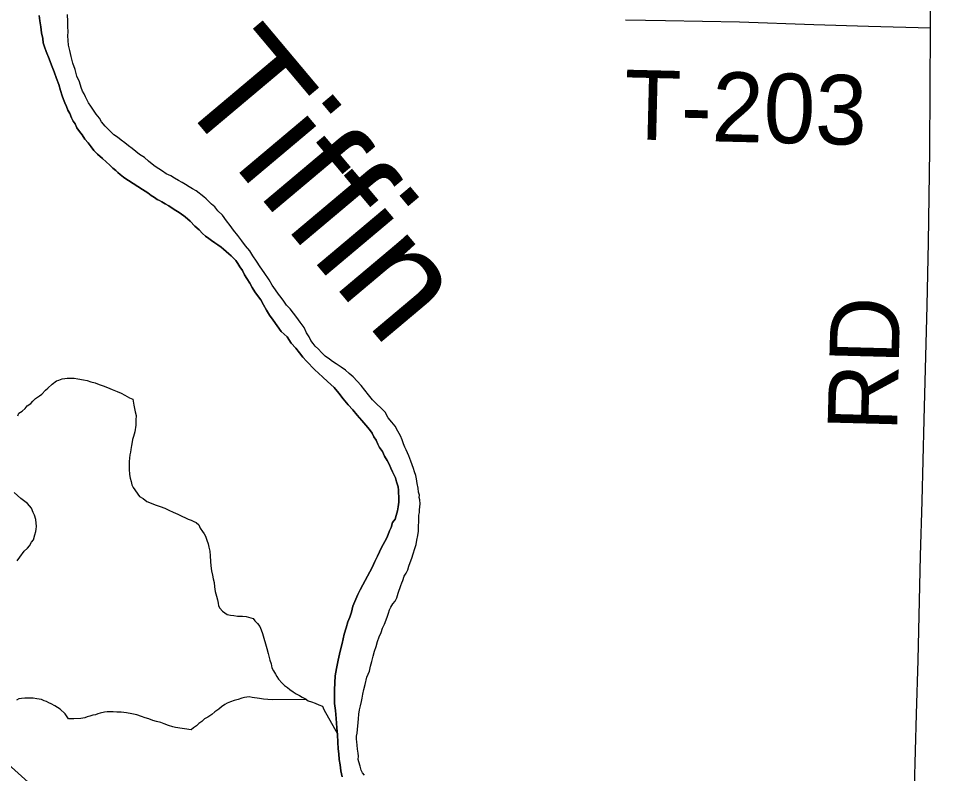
# Model space of a CAD drawing. Extents: x 2.1 to 73.9, y 4 to 26.
# Drawn here: x 47.8205 to 48.1962, y 24.0542 to 24.3627 of the extents above; entities that cross this region are included whole.
import ezdxf

# ---------------------------------------------------------------- set-up
doc = ezdxf.new("R2010")
doc.units = 0
for name, color, linetype in [('GM_X_County_Road', 7, 'Continuous'), ('GM_X_County_Road_Text', 7, 'Continuous'), ('GM_X_Major_River', 7, 'Continuous'), ('GM_X_Major_River_Text', 7, 'Continuous'), ('GM_X_Minor_River', 7, 'Continuous'), ('GM_X_State_Route', 7, 'Continuous'), ('GM_X_Township_Road', 7, 'Continuous'), ('GM_X_Township_Road_Text', 7, 'Continuous')]:
    doc.layers.add(name, color=color, linetype=linetype)

msp = doc.modelspace()

# ---------------------------------------------------------------- linework, layer by layer
at = {"layer": 'GM_X_County_Road'}
for points in [[(48.19325, 24.35883), (48.19329, 24.38494), (48.1935, 24.41821), (48.19357, 24.44027), (48.19356, 24.46205), (48.19359, 24.48068), (48.19358, 24.49156), (48.19371, 24.51674), (48.19388, 24.55155), (48.19407, 24.57673), (48.19423, 24.59599), (48.19435, 24.61584), (48.19457, 24.64257), (48.19491, 24.6777), (48.19507, 24.69386), (48.1954, 24.72618), (48.19554, 24.74546), (48.1958, 24.76317), (48.19622, 24.80171)], [(48.18678, 24.0485), (48.18765, 24.07851), (48.18821, 24.10057), (48.18883, 24.12481), (48.18921, 24.14315), (48.18984, 24.16551), (48.19072, 24.19876), (48.1919, 24.24538), (48.19247, 24.27117), (48.19307, 24.30878), (48.19325, 24.35883)]]:
    msp.add_lwpolyline(points, dxfattribs=at)
at = {"layer": 'GM_X_Major_River'}
for points in [[(47.82904, 24.36382), (47.82937, 24.36172), (47.82969, 24.35925), (47.83, 24.35677), (47.83052, 24.35448), (47.83066, 24.35277), (47.83119, 24.35104), (47.8319, 24.34913), (47.83316, 24.34625), (47.83404, 24.34357), (47.83511, 24.34088), (47.83618, 24.3382), (47.83707, 24.3357), (47.83777, 24.33322), (47.83848, 24.33111), (47.83901, 24.32958), (47.83954, 24.32824), (47.84026, 24.3267), (47.8408, 24.32517), (47.84152, 24.32382), (47.84224, 24.32209), (47.84296, 24.32075)], [(47.84296, 24.32075), (47.84224, 24.32209), (47.84152, 24.32382), (47.8408, 24.32517), (47.84026, 24.3267), (47.83954, 24.32824), (47.83901, 24.32958), (47.83848, 24.33111), (47.83777, 24.33322), (47.83707, 24.3357), (47.83618, 24.3382), (47.83511, 24.34088), (47.83404, 24.34357), (47.83316, 24.34625), (47.8319, 24.34913), (47.83119, 24.35104), (47.83066, 24.35277), (47.83052, 24.35448), (47.83, 24.35677), (47.82969, 24.35925), (47.82937, 24.36172), (47.82904, 24.36382)], [(47.94448, 24.22627), (47.94318, 24.22763), (47.94189, 24.2288), (47.94096, 24.22996), (47.94004, 24.23113), (47.93932, 24.23266), (47.93822, 24.23421), (47.93733, 24.23651), (47.93567, 24.23864), (47.93439, 24.24057), (47.93292, 24.24232), (47.93163, 24.24406), (47.93015, 24.24562), (47.92905, 24.24716), (47.92795, 24.24871), (47.92685, 24.25007), (47.92556, 24.25181), (47.92428, 24.25374), (47.923, 24.25586), (47.92099, 24.25895), (47.91934, 24.26127), (47.91788, 24.26359), (47.91641, 24.26571), (47.91514, 24.26783), (47.91329, 24.26978), (47.91182, 24.27191), (47.91017, 24.27404), (47.90851, 24.27617), (47.90704, 24.2781), (47.90557, 24.28004), (47.90392, 24.28236), (47.90206, 24.28412), (47.90077, 24.28567), (47.89947, 24.28684), (47.89817, 24.28801), (47.89725, 24.28898), (47.89632, 24.28977), (47.89315, 24.29232), (47.89165, 24.29311), (47.89034, 24.29391), (47.88885, 24.29489), (47.88754, 24.29569), (47.88604, 24.29648), (47.88435, 24.29748), (47.88286, 24.29846), (47.88098, 24.29927), (47.87949, 24.30026), (47.87799, 24.30125), (47.8765, 24.30223), (47.87519, 24.30322), (47.8737, 24.30439), (47.87203, 24.30595), (47.86997, 24.30715), (47.86848, 24.30832), (47.86699, 24.3095), (47.8655, 24.31068), (47.86401, 24.31185), (47.86252, 24.31303), (47.86103, 24.31421), (47.85954, 24.3152), (47.85824, 24.31656), (47.85713, 24.31754), (47.85602, 24.3187), (47.85454, 24.32045), (47.85363, 24.32199), (47.85234, 24.32354), (47.85124, 24.32528), (47.85014, 24.32683), (47.84923, 24.32818), (47.8485, 24.32953), (47.84796, 24.33068), (47.84742, 24.33183), (47.84669, 24.33299), (47.84616, 24.33452), (47.84546, 24.33682), (47.84438, 24.33913), (47.84368, 24.3418), (47.8428, 24.34448), (47.84211, 24.34716), (47.8416, 24.34964), (47.84108, 24.35174), (47.84094, 24.35364), (47.8408, 24.35555), (47.84084, 24.35725), (47.84071, 24.35935), (47.84076, 24.36143), (47.84064, 24.36428)], [(47.94448, 24.22627), (47.94318, 24.22763), (47.94189, 24.2288), (47.94096, 24.22996), (47.94004, 24.23113), (47.93932, 24.23266), (47.93822, 24.23421), (47.93733, 24.23651), (47.93567, 24.23864), (47.93439, 24.24057), (47.93292, 24.24232), (47.93163, 24.24406), (47.93015, 24.24562), (47.92905, 24.24716), (47.92795, 24.24871), (47.92685, 24.25007), (47.92556, 24.25181), (47.92428, 24.25374), (47.923, 24.25586), (47.92099, 24.25895), (47.91934, 24.26127), (47.91788, 24.26359), (47.91641, 24.26571), (47.91514, 24.26783), (47.91329, 24.26978), (47.91182, 24.27191), (47.91017, 24.27404), (47.90851, 24.27617), (47.90704, 24.2781), (47.90557, 24.28004), (47.90392, 24.28236), (47.90206, 24.28412), (47.90077, 24.28567), (47.89947, 24.28684), (47.89817, 24.28801), (47.89725, 24.28898), (47.89632, 24.28977), (47.89315, 24.29232), (47.89165, 24.29311), (47.89034, 24.29391), (47.88885, 24.29489), (47.88754, 24.29569), (47.88604, 24.29648), (47.88435, 24.29748), (47.88286, 24.29846), (47.88098, 24.29927), (47.87949, 24.30026), (47.87799, 24.30125), (47.8765, 24.30223), (47.87519, 24.30322), (47.8737, 24.30439), (47.87203, 24.30595), (47.86997, 24.30715), (47.86848, 24.30832), (47.86699, 24.3095), (47.8655, 24.31068), (47.86401, 24.31185), (47.86252, 24.31303), (47.86103, 24.31421), (47.85954, 24.3152), (47.85824, 24.31656), (47.85713, 24.31754), (47.85602, 24.3187), (47.85454, 24.32045), (47.85363, 24.32199), (47.85234, 24.32354), (47.85124, 24.32528), (47.85014, 24.32683), (47.84923, 24.32818), (47.8485, 24.32953), (47.84796, 24.33068), (47.84742, 24.33183), (47.84669, 24.33299), (47.84616, 24.33452), (47.84546, 24.33682), (47.84438, 24.33913), (47.84368, 24.3418), (47.8428, 24.34448), (47.84211, 24.34716), (47.8416, 24.34964), (47.84108, 24.35174), (47.84094, 24.35364), (47.8408, 24.35555), (47.84084, 24.35725), (47.84071, 24.35935), (47.84076, 24.36143), (47.84064, 24.36428)], [(47.84296, 24.32075), (47.84369, 24.31959), (47.84441, 24.31805), (47.84552, 24.3165), (47.84662, 24.31515), (47.84772, 24.31341), (47.84901, 24.31186), (47.8503, 24.3103), (47.8514, 24.30876), (47.85288, 24.3072), (47.85492, 24.30544), (47.85641, 24.30407), (47.85789, 24.30271), (47.85919, 24.30153), (47.86031, 24.30056), (47.86124, 24.29977), (47.86217, 24.29899), (47.86347, 24.29782), (47.8644, 24.29722), (47.86552, 24.29644), (47.87132, 24.29287), (47.87338, 24.29149), (47.87487, 24.29031), (47.87618, 24.28952), (47.8773, 24.28873), (47.87824, 24.28833), (47.87917, 24.28774), (47.88048, 24.28694), (47.88198, 24.28615), (47.88385, 24.28496), (47.88665, 24.28318), (47.8887, 24.28161), (47.89075, 24.27985), (47.8926, 24.2779), (47.89446, 24.27633), (47.89575, 24.27478), (47.89705, 24.2738), (47.89836, 24.27282), (47.89948, 24.27203), (47.90078, 24.27105), (47.90209, 24.27025), (47.9034, 24.26927), (47.90433, 24.26849), (47.90544, 24.26751), (47.90656, 24.26653), (47.90749, 24.26575), (47.90841, 24.26478), (47.90934, 24.2638), (47.91026, 24.26264), (47.91098, 24.26129), (47.91208, 24.25975), (47.91299, 24.25802), (47.9139, 24.25647), (47.91518, 24.25454), (47.91609, 24.25281), (47.91718, 24.25107), (47.91828, 24.24953), (47.91957, 24.24779), (47.92066, 24.24567), (47.92193, 24.24355), (47.92321, 24.24143), (47.92468, 24.23949), (47.92633, 24.23717), (47.92798, 24.23485), (47.9304, 24.2327), (47.93204, 24.23), (47.93389, 24.22806), (47.93536, 24.22612), (47.93683, 24.22437), (47.93831, 24.22263), (47.94164, 24.21912), (47.94313, 24.21776), (47.94499, 24.21619), (47.94684, 24.21444), (47.94963, 24.2119), (47.95147, 24.20957), (47.95331, 24.20725), (47.95534, 24.20492), (47.95718, 24.20278), (47.95903, 24.20065), (47.96087, 24.19851), (47.96253, 24.19657), (47.96401, 24.19482), (47.96511, 24.19328), (47.96583, 24.19174), (47.96675, 24.19039), (47.96747, 24.18885), (47.96819, 24.1875), (47.96929, 24.18577), (47.97019, 24.18385), (47.97129, 24.18211), (47.97201, 24.18057), (47.97273, 24.17904), (47.97345, 24.1775), (47.97399, 24.17635), (47.97472, 24.175), (47.97506, 24.17347), (47.97576, 24.17136), (47.97592, 24.17003), (47.9759, 24.16908), (47.97604, 24.16718)], [(47.97604, 24.16718), (47.9759, 24.16908), (47.97592, 24.17003), (47.97576, 24.17136), (47.97506, 24.17347), (47.97472, 24.175), (47.97399, 24.17635), (47.97345, 24.1775), (47.97273, 24.17904), (47.97201, 24.18057), (47.97129, 24.18211), (47.97019, 24.18385), (47.96929, 24.18577), (47.96819, 24.1875), (47.96747, 24.18885), (47.96675, 24.19039), (47.96583, 24.19174), (47.96511, 24.19328), (47.96401, 24.19482), (47.96253, 24.19657), (47.96087, 24.19851), (47.95903, 24.20065), (47.95718, 24.20278), (47.95534, 24.20492), (47.95331, 24.20725), (47.95147, 24.20957), (47.94963, 24.2119), (47.94684, 24.21444), (47.94499, 24.21619), (47.94313, 24.21776), (47.94164, 24.21912), (47.93831, 24.22263), (47.93683, 24.22437), (47.93536, 24.22612), (47.93389, 24.22806), (47.93204, 24.23), (47.9304, 24.2327), (47.92798, 24.23485), (47.92633, 24.23717), (47.92468, 24.23949), (47.92321, 24.24143), (47.92193, 24.24355), (47.92066, 24.24567), (47.91957, 24.24779), (47.91828, 24.24953), (47.91718, 24.25107), (47.91609, 24.25281), (47.91518, 24.25454), (47.9139, 24.25647), (47.91299, 24.25802), (47.91208, 24.25975), (47.91098, 24.26129), (47.91026, 24.26264), (47.90934, 24.2638), (47.90841, 24.26478), (47.90749, 24.26575), (47.90656, 24.26653), (47.90544, 24.26751), (47.90433, 24.26849), (47.9034, 24.26927), (47.90209, 24.27025), (47.90078, 24.27105), (47.89948, 24.27203), (47.89836, 24.27282), (47.89705, 24.2738), (47.89575, 24.27478), (47.89446, 24.27633), (47.8926, 24.2779), (47.89075, 24.27985), (47.8887, 24.28161), (47.88665, 24.28318), (47.88385, 24.28496), (47.88198, 24.28615), (47.88048, 24.28694), (47.87917, 24.28774), (47.87824, 24.28833), (47.8773, 24.28873), (47.87618, 24.28952), (47.87487, 24.29031), (47.87338, 24.29149), (47.87132, 24.29287), (47.86552, 24.29644), (47.8644, 24.29722), (47.86347, 24.29782), (47.86217, 24.29899), (47.86124, 24.29977), (47.86031, 24.30056), (47.85919, 24.30153), (47.85789, 24.30271), (47.85641, 24.30407), (47.85492, 24.30544), (47.85288, 24.3072), (47.8514, 24.30876), (47.8503, 24.3103), (47.84901, 24.31186), (47.84772, 24.31341), (47.84662, 24.31515), (47.84552, 24.3165), (47.84441, 24.31805), (47.84369, 24.31959), (47.84296, 24.32075)], [(47.95946, 24.05996), (47.9595, 24.06129), (47.95934, 24.06262), (47.95919, 24.06415), (47.95904, 24.06586), (47.95889, 24.06719), (47.95873, 24.06834), (47.95875, 24.06947), (47.95898, 24.0708), (47.95951, 24.07667), (47.95974, 24.07856), (47.95998, 24.08026), (47.9604, 24.08196), (47.96082, 24.08366), (47.96105, 24.08498), (47.96128, 24.08668), (47.96171, 24.08857), (47.96233, 24.09064), (47.96298, 24.09366), (47.96399, 24.09611), (47.96442, 24.09818), (47.96504, 24.10007), (47.96547, 24.10214), (47.96609, 24.10422), (47.96671, 24.1061), (47.96733, 24.10817), (47.96795, 24.11005), (47.96876, 24.11193), (47.96937, 24.11362), (47.97017, 24.11531), (47.97078, 24.11701), (47.97139, 24.11851), (47.9718, 24.11983), (47.97222, 24.12115), (47.97282, 24.12227), (47.97361, 24.12358), (47.97458, 24.12469), (47.97519, 24.12601), (47.97581, 24.12789), (47.97684, 24.13109), (47.97724, 24.13222), (47.97765, 24.13316), (47.97826, 24.13485), (47.97905, 24.13616), (47.97966, 24.13747), (47.98008, 24.13898), (47.98068, 24.14048), (47.9813, 24.14218), (47.98191, 24.14406), (47.98254, 24.14613), (47.98315, 24.14783), (47.98338, 24.14953), (47.98381, 24.15142), (47.98405, 24.15331), (47.9841, 24.15559), (47.98414, 24.15691), (47.98416, 24.15786), (47.98419, 24.15881), (47.98421, 24.15976), (47.98443, 24.16089), (47.98446, 24.16203), (47.98467, 24.16316), (47.98471, 24.16449), (47.98456, 24.16601), (47.98439, 24.16697), (47.98441, 24.16792), (47.98407, 24.16925), (47.98392, 24.17078), (47.98358, 24.17268), (47.98325, 24.17459), (47.98291, 24.17593), (47.98238, 24.17746), (47.98203, 24.1788), (47.9815, 24.18033), (47.98097, 24.18186), (47.98007, 24.18397), (47.97954, 24.18532), (47.97899, 24.18647), (47.97845, 24.18762), (47.97792, 24.18896), (47.97739, 24.1905), (47.97667, 24.19222), (47.97558, 24.19415), (47.97449, 24.19608), (47.9732, 24.19782), (47.97173, 24.19956), (47.97046, 24.20187), (47.96527, 24.20694), (47.96361, 24.20888), (47.96214, 24.21082), (47.96066, 24.21276), (47.959, 24.21451), (47.95733, 24.21626), (47.95566, 24.21763), (47.95417, 24.219), (47.95249, 24.22018), (47.95044, 24.22156), (47.94894, 24.22255), (47.94764, 24.22353), (47.94596, 24.22471), (47.94448, 24.22627)], [(47.95946, 24.05996), (47.9595, 24.06129), (47.95934, 24.06262), (47.95919, 24.06415), (47.95904, 24.06586), (47.95889, 24.06719), (47.95873, 24.06834), (47.95875, 24.06947), (47.95898, 24.0708), (47.95951, 24.07667), (47.95974, 24.07856), (47.95998, 24.08026), (47.9604, 24.08196), (47.96082, 24.08366), (47.96105, 24.08498), (47.96128, 24.08668), (47.96171, 24.08857), (47.96233, 24.09064), (47.96298, 24.09366), (47.96399, 24.09611), (47.96442, 24.09818), (47.96504, 24.10007), (47.96547, 24.10214), (47.96609, 24.10422), (47.96671, 24.1061), (47.96733, 24.10817), (47.96795, 24.11005), (47.96876, 24.11193), (47.96937, 24.11362), (47.97017, 24.11531), (47.97078, 24.11701), (47.97139, 24.11851), (47.9718, 24.11983), (47.97222, 24.12115), (47.97282, 24.12227), (47.97361, 24.12358), (47.97458, 24.12469), (47.97519, 24.12601), (47.97581, 24.12789), (47.97684, 24.13109), (47.97724, 24.13222), (47.97765, 24.13316), (47.97826, 24.13485), (47.97905, 24.13616), (47.97966, 24.13747), (47.98008, 24.13898), (47.98068, 24.14048), (47.9813, 24.14218), (47.98191, 24.14406), (47.98254, 24.14613), (47.98315, 24.14783), (47.98338, 24.14953), (47.98381, 24.15142), (47.98405, 24.15331), (47.9841, 24.15559), (47.98414, 24.15691), (47.98416, 24.15786), (47.98419, 24.15881), (47.98421, 24.15976), (47.98443, 24.16089), (47.98446, 24.16203), (47.98467, 24.16316), (47.98471, 24.16449), (47.98456, 24.16601), (47.98439, 24.16697), (47.98441, 24.16792), (47.98407, 24.16925), (47.98392, 24.17078), (47.98358, 24.17268), (47.98325, 24.17459), (47.98291, 24.17593), (47.98238, 24.17746), (47.98203, 24.1788), (47.9815, 24.18033), (47.98097, 24.18186), (47.98007, 24.18397), (47.97954, 24.18532), (47.97899, 24.18647), (47.97845, 24.18762), (47.97792, 24.18896), (47.97739, 24.1905), (47.97667, 24.19222), (47.97558, 24.19415), (47.97449, 24.19608), (47.9732, 24.19782), (47.97173, 24.19956), (47.97046, 24.20187), (47.96527, 24.20694), (47.96361, 24.20888), (47.96214, 24.21082), (47.96066, 24.21276), (47.959, 24.21451), (47.95733, 24.21626), (47.95566, 24.21763), (47.95417, 24.219), (47.95249, 24.22018), (47.95044, 24.22156), (47.94894, 24.22255), (47.94764, 24.22353), (47.94596, 24.22471), (47.94448, 24.22627)], [(47.97604, 24.16718), (47.97599, 24.16509), (47.97575, 24.1632), (47.97552, 24.1615), (47.9749, 24.15962), (47.97448, 24.15811), (47.9735, 24.1568), (47.97287, 24.15473), (47.97227, 24.15342), (47.97166, 24.15191), (47.97106, 24.1506), (47.97026, 24.1491), (47.96966, 24.14779), (47.96886, 24.14629), (47.96807, 24.14479), (47.96726, 24.1431), (47.96626, 24.14085), (47.96506, 24.13841), (47.96127, 24.1313), (47.96026, 24.12923), (47.95927, 24.12736), (47.95846, 24.12548), (47.95725, 24.12267), (47.95662, 24.12021), (47.956, 24.11814), (47.95519, 24.11626), (47.95456, 24.11381), (47.95373, 24.11118), (47.95288, 24.1074), (47.95203, 24.1042), (47.95118, 24.10061), (47.95053, 24.09721), (47.95007, 24.09418), (47.94981, 24.09134), (47.94974, 24.0885), (47.94967, 24.08565), (47.94978, 24.0828), (47.95009, 24.07995), (47.95039, 24.07671), (47.95067, 24.07291), (47.95098, 24.07005), (47.9511, 24.06701), (47.95122, 24.06435), (47.95154, 24.06225), (47.95168, 24.05997), (47.952, 24.05788), (47.95232, 24.0554), (47.95283, 24.05292)], [(47.95283, 24.05292), (47.95232, 24.0554), (47.952, 24.05788), (47.95168, 24.05997), (47.95154, 24.06225), (47.95122, 24.06435), (47.9511, 24.06701), (47.95098, 24.07005), (47.95067, 24.07291), (47.95039, 24.07671), (47.95009, 24.07995), (47.94978, 24.0828), (47.94967, 24.08565), (47.94974, 24.0885), (47.94981, 24.09134), (47.95007, 24.09418), (47.95053, 24.09721), (47.95118, 24.10061), (47.95203, 24.1042), (47.95288, 24.1074), (47.95373, 24.11118), (47.95456, 24.11381), (47.95519, 24.11626), (47.956, 24.11814), (47.95662, 24.12021), (47.95725, 24.12267), (47.95846, 24.12548), (47.95927, 24.12736), (47.96026, 24.12923), (47.96127, 24.1313), (47.96506, 24.13841), (47.96626, 24.14085), (47.96726, 24.1431), (47.96807, 24.14479), (47.96886, 24.14629), (47.96966, 24.14779), (47.97026, 24.1491), (47.97106, 24.1506), (47.97166, 24.15191), (47.97227, 24.15342), (47.97287, 24.15473), (47.9735, 24.1568), (47.97448, 24.15811), (47.9749, 24.15962), (47.97552, 24.1615), (47.97575, 24.1632), (47.97599, 24.16509), (47.97604, 24.16718)], [(47.96196, 24.05364), (47.96123, 24.0546), (47.96068, 24.05557), (47.96016, 24.05729), (47.95963, 24.05901), (47.95946, 24.05996)], [(47.96196, 24.05364), (47.96123, 24.0546), (47.96068, 24.05557), (47.96016, 24.05729), (47.95963, 24.05901), (47.95946, 24.05996)]]:
    msp.add_lwpolyline(points, dxfattribs=at)
at = {"layer": 'GM_X_Minor_River'}
for points in [[(47.82037, 24.20038), (47.82077, 24.20151), (47.82212, 24.20223), (47.82329, 24.20334), (47.82408, 24.20446), (47.82562, 24.20537), (47.8264, 24.2063), (47.82757, 24.20741), (47.82912, 24.20851), (47.83009, 24.20925), (47.83165, 24.21091), (47.83262, 24.21165), (47.83437, 24.21331), (47.83611, 24.2146), (47.83707, 24.21495), (47.83841, 24.21549), (47.83955, 24.21565), (47.84051, 24.21581), (47.84165, 24.21579), (47.84335, 24.21574), (47.84487, 24.21551), (47.84714, 24.21508), (47.84865, 24.21485), (47.85016, 24.21424), (47.85185, 24.21382), (47.85355, 24.2132), (47.85524, 24.21259), (47.85694, 24.21198), (47.85882, 24.21117), (47.86088, 24.21036), (47.86257, 24.20956), (47.86407, 24.20876), (47.86595, 24.20776), (47.86726, 24.20716), (47.86777, 24.20468), (47.86827, 24.20201), (47.86861, 24.20048), (47.86857, 24.19858), (47.86851, 24.1965), (47.86807, 24.19385)], [(47.86807, 24.19385), (47.86764, 24.19196), (47.86722, 24.19064), (47.86701, 24.1897), (47.86678, 24.18819), (47.86655, 24.18667), (47.86634, 24.18554), (47.86612, 24.18441), (47.86589, 24.18308), (47.86586, 24.18176), (47.86582, 24.18005), (47.86578, 24.17853), (47.86592, 24.17644), (47.86626, 24.17491), (47.8666, 24.17357), (47.86695, 24.17224), (47.86749, 24.17108), (47.87006, 24.16741), (47.87156, 24.16661), (47.87305, 24.16544), (47.87474, 24.16463), (47.87643, 24.16402), (47.8785, 24.1634), (47.88038, 24.16259), (47.88207, 24.16179), (47.88376, 24.16099), (47.88564, 24.16018), (47.88733, 24.15938), (47.88883, 24.15877), (47.88996, 24.15817), (47.89109, 24.15776), (47.89221, 24.15716), (47.89315, 24.15676), (47.89427, 24.15578), (47.8948, 24.15444), (47.89572, 24.15309), (47.89645, 24.15212), (47.897, 24.15116), (47.89753, 24.14962), (47.89806, 24.14809), (47.89841, 24.14675), (47.89874, 24.14504), (47.89889, 24.14314), (47.89902, 24.14085), (47.89916, 24.13914), (47.89949, 24.13705), (47.89983, 24.13533), (47.90017, 24.1338), (47.90051, 24.13227), (47.90066, 24.13056), (47.90099, 24.12865), (47.90151, 24.12674), (47.90185, 24.12521), (47.9022, 24.12388), (47.90236, 24.12273), (47.90291, 24.12177), (47.90401, 24.1206), (47.90588, 24.11923), (47.9072, 24.119), (47.90853, 24.11878), (47.91004, 24.11855), (47.91213, 24.1185), (47.91365, 24.11846), (47.91648, 24.11763), (47.91721, 24.11666), (47.91832, 24.11549), (47.91924, 24.11433), (47.91978, 24.11299), (47.92031, 24.11146), (47.92083, 24.10954), (47.92153, 24.10725), (47.92205, 24.10534), (47.92257, 24.10324), (47.92326, 24.10056), (47.92379, 24.09903), (47.92413, 24.0975), (47.92486, 24.09615), (47.92559, 24.09481), (47.92613, 24.09384), (47.92687, 24.09287), (47.92834, 24.09113), (47.92927, 24.09016), (47.93058, 24.08936), (47.93151, 24.08858), (47.93281, 24.0876), (47.93412, 24.08681), (47.93544, 24.0862), (47.93655, 24.08541), (47.93787, 24.08481), (47.93899, 24.08402), (47.94031, 24.08361), (47.94181, 24.083), (47.94332, 24.08239), (47.94482, 24.08179), (47.94536, 24.08045), (47.95094, 24.07043)], [(47.82001, 24.14116), (47.82119, 24.14265), (47.82296, 24.14507), (47.82432, 24.14636), (47.8251, 24.14729), (47.8259, 24.14879), (47.82668, 24.14972), (47.82731, 24.15179), (47.82772, 24.15311), (47.82774, 24.15406), (47.82796, 24.15519), (47.82765, 24.15805), (47.82713, 24.15977), (47.82659, 24.16092), (47.82587, 24.16265), (47.82421, 24.16459), (47.8216, 24.16655), (47.81882, 24.16909)], [(47.93837, 24.08446), (47.92456, 24.08439), (47.92247, 24.08444), (47.92077, 24.08468), (47.91907, 24.08491), (47.91604, 24.08537), (47.91491, 24.08559), (47.91395, 24.08542), (47.913, 24.08525), (47.91185, 24.08509), (47.91032, 24.08456), (47.90879, 24.08403), (47.90726, 24.0835), (47.90591, 24.08297), (47.90495, 24.08242), (47.9036, 24.08151), (47.90243, 24.08059), (47.90089, 24.07949), (47.89953, 24.07838), (47.89798, 24.07728), (47.89663, 24.07656), (47.89547, 24.07545), (47.89431, 24.07472), (47.89333, 24.0738), (47.89217, 24.07288), (47.8912, 24.07214), (47.88477, 24.07306), (47.88363, 24.07328), (47.88194, 24.0739), (47.88006, 24.07451), (47.87874, 24.07512), (47.87704, 24.07554), (47.87553, 24.07596), (47.87384, 24.07657), (47.87233, 24.07699), (47.87083, 24.0776), (47.86894, 24.07821), (47.86687, 24.07865), (47.86479, 24.07908), (47.86251, 24.07933), (47.86081, 24.07937), (47.85929, 24.07941), (47.85796, 24.07944), (47.85682, 24.07947), (47.85568, 24.07931), (47.85396, 24.07897), (47.853, 24.07862), (47.85204, 24.07826), (47.8509, 24.0781), (47.84975, 24.07775), (47.8486, 24.0774), (47.84764, 24.07705), (47.84611, 24.07671), (47.84326, 24.07659), (47.84098, 24.07665), (47.8397, 24.07858), (47.83766, 24.08053), (47.83542, 24.08191), (47.83392, 24.08271), (47.83298, 24.08311), (47.83204, 24.08371), (47.8311, 24.08392), (47.82998, 24.08452), (47.82808, 24.08476), (47.82657, 24.08499), (47.82467, 24.08503), (47.82315, 24.08507), (47.82182, 24.08492), (47.82067, 24.08476), (47.81971, 24.08421)]]:
    msp.add_lwpolyline(points, dxfattribs=at)
at = {"layer": 'GM_X_State_Route'}
msp.add_lwpolyline([(47.6941, 24.19204), (47.69455, 24.19073), (47.69636, 24.18546), (47.69818, 24.18085), (47.70031, 24.17604), (47.7029, 24.17075), (47.70552, 24.16582), (47.70786, 24.16182), (47.71055, 24.15765), (47.7134, 24.1536), (47.71679, 24.14918), (47.72074, 24.14439), (47.72484, 24.13974), (47.72934, 24.13505), (47.73337, 24.13119), (47.74165, 24.12369), (47.74824, 24.11798), (47.75825, 24.10914), (47.78846, 24.08276), (47.80409, 24.06899), (47.82588, 24.04952), (47.83546, 24.04064), (47.85175, 24.02534)], dxfattribs=at)
at = {"layer": 'GM_X_Township_Road'}
msp.add_lwpolyline([(48.06872, 24.36205), (48.08505, 24.36184), (48.11522, 24.36127), (48.14567, 24.36024), (48.16794, 24.35957), (48.19325, 24.35883)], dxfattribs=at)

# ---------------------------------------------------------------- texts
at = {"layer": 'GM_X_County_Road_Text'}
msp.add_text('RD', height=0.028409, rotation=88.5184, dxfattribs=at).set_placement((48.17962, 24.19379))
at = {"layer": 'GM_X_Major_River_Text'}
msp.add_text('Tiffin', height=0.047369, rotation=310.0441, dxfattribs=at).set_placement((47.88321, 24.33248))
at = {"layer": 'GM_X_Township_Road_Text'}
msp.add_text('T-203', height=0.028409, rotation=358.5952, dxfattribs=at).set_placement((48.06781, 24.31338))

doc.saveas('drawing.dxf')
